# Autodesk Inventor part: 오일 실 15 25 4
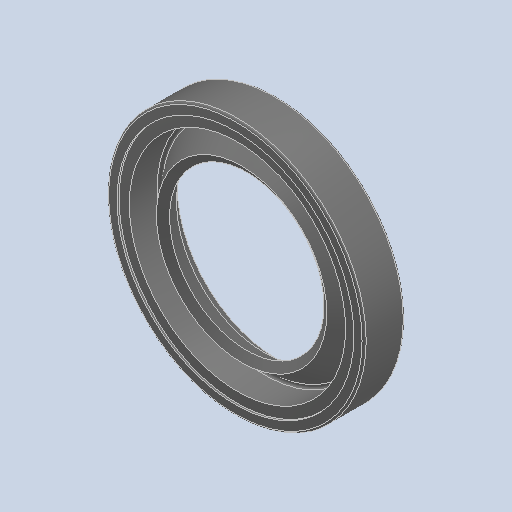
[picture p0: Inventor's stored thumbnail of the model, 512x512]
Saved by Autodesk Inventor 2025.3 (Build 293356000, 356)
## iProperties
Created: 2025-10
Part Number: 오일 실 15 25 4
Material: 고무
Description: 오일 실 - 비스프링, 조립 GA
Document SubType Name: Modeling
Designer: USER
Density: 0.93 g/cm^3
Appearance: 기본값
Author: jhkim
Sending System: Autodesk Inventor 2026
Preprocessor: ST-DEVELOPER v20.1
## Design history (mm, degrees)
feature "Solid1"
node "솔리드1"
